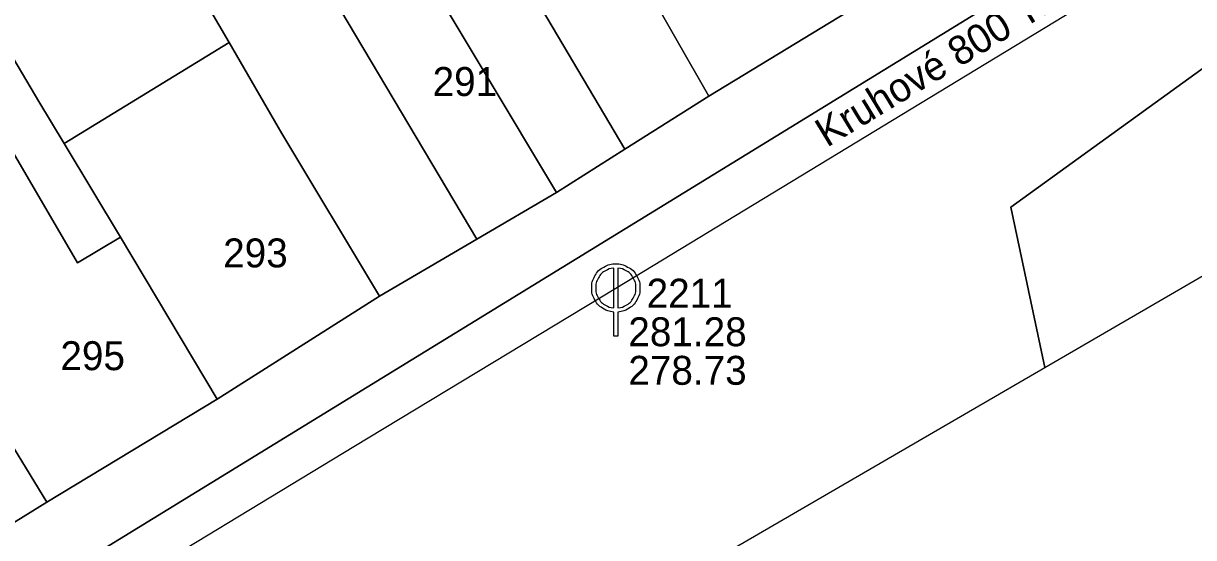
# Model space of a CAD drawing. Extents: x -571312 to -571060, y -1087128 to -1086933.
# Drawn here: x -571153.9 to -571093.3, y -1087060.8 to -1087034.1 of the extents above; entities that cross this region are included whole.
import ezdxf

# ---------------------------------------------------------------- set-up
doc = ezdxf.new("R2010")
doc.units = 0
for name, color, linetype in [('Default', 7, 'Continuous'), ('Kanalizační stoka', 7, 'Continuous'), ('Kanalizační šachta', 7, 'Continuous'), ('Parcela-polygon', 7, 'Continuous'), ('Parcela-text', 7, 'Continuous'), ('Popis kmenové stoky', 7, 'Continuous'), ('Popis šachty', 7, 'Continuous')]:
    doc.layers.add(name, color=color, linetype=linetype)

msp = doc.modelspace()

# ---------------------------------------------------------------- linework, layer by layer
at = {"layer": 'Default'}
for points in [[(-571123.323, -1087049.108), (-571123.581, -1087049.09), (-571123.843, -1087048.944), (-571124.14, -1087048.78), (-571124.305, -1087048.483), (-571124.47, -1087048.185), (-571124.47, -1087047.86), (-571124.47, -1087047.533), (-571124.302, -1087047.233), (-571124.133, -1087046.932), (-571123.835, -1087046.771), (-571123.537, -1087046.61), (-571123.22, -1087046.61), (-571122.905, -1087046.61), (-571122.606, -1087046.771), (-571122.307, -1087046.932), (-571122.138, -1087047.233), (-571121.97, -1087047.533), (-571121.97, -1087047.86), (-571121.97, -1087048.185), (-571122.135, -1087048.483), (-571122.3, -1087048.78), (-571122.597, -1087048.944), (-571122.859, -1087049.09), (-571123.117, -1087049.108)], [(-571123.323, -1087046.822), (-571123.52, -1087046.839), (-571123.735, -1087046.954), (-571123.984, -1087047.089), (-571124.123, -1087047.339), (-571124.262, -1087047.589), (-571124.262, -1087047.86), (-571124.262, -1087048.131), (-571124.126, -1087048.378), (-571123.989, -1087048.624), (-571123.74, -1087048.761), (-571123.528, -1087048.881), (-571123.323, -1087048.895)], [(-571123.117, -1087048.895), (-571122.912, -1087048.881), (-571122.698, -1087048.761), (-571122.451, -1087048.624), (-571122.314, -1087048.378), (-571122.178, -1087048.131), (-571122.178, -1087047.86), (-571122.178, -1087047.589), (-571122.318, -1087047.339), (-571122.458, -1087047.089), (-571122.707, -1087046.954), (-571122.92, -1087046.839), (-571123.117, -1087046.822)]]:
    msp.add_open_spline(points, degree=3, dxfattribs=at)
at = {"layer": 'Kanalizační stoka'}
for points in [[(-571123.22, -1087047.86), (-571104.524, -1087036.501), (-571085.827, -1087025.142)], [(-571150.38, -1087064.31), (-571136.8, -1087056.085), (-571123.22, -1087047.86)]]:
    msp.add_lwpolyline(points, dxfattribs=at)
at = {"layer": 'Kanalizační šachta'}
for points in [[(-571123.323, -1087048.895), (-571123.323, -1087046.822)], [(-571123.117, -1087046.822), (-571123.117, -1087048.895)], [(-571123.117, -1087049.108), (-571123.117, -1087050.36), (-571123.323, -1087050.36), (-571123.323, -1087049.108)]]:
    msp.add_lwpolyline(points, dxfattribs=at)
at = {"layer": 'Parcela-polygon'}
msp.add_line((-571100.979, -1087051.983), (-571073.23, -1087035.86), dxfattribs=at)
for points in [[(-571238.048, -1087115.573), (-571084.13, -1087021.07), (-571088.23, -1087015.62), (-571087.4, -1087014.88), (-571089.5, -1087012.31), (-571106.96, -1086996.89), (-571110.31, -1086993.17), (-571111.37, -1086999.41), (-571102.11, -1087007.86), (-571094.7, -1087015.4), (-571092.99, -1087017.97), (-571091.96, -1087020.97), (-571094.14, -1087023.09), (-571099.22, -1087026.2), (-571108.52, -1087031.9), (-571118.39, -1087037.91), (-571122.75, -1087040.66), (-571126.3, -1087042.9), (-571130.43, -1087045.33), (-571135.47, -1087048.29), (-571143.89, -1087053.63), (-571152.72, -1087058.97), (-571161.7, -1087064.52)], [(-571100.979, -1087051.983), (-571102.73, -1087043.67), (-571081.09, -1087028.01), (-571079.74, -1087027.03), (-571084.13, -1087021.07), (-571238.048, -1087115.573)], [(-571073.23, -1087035.86), (-571079.74, -1087027.03), (-571081.09, -1087028.01), (-571102.73, -1087043.67), (-571100.979, -1087051.983)], [(-571238.048, -1087115.573), (-571230.994, -1087127.523), (-571100.979, -1087051.983)]]:
    msp.add_lwpolyline(points, dxfattribs=at)
for points in [[(-571123.41, -1087006.48), (-571133.26, -1087012.24), (-571128.44, -1087020.34), (-571125.58, -1087018.67), (-571124.4, -1087020.72), (-571123.13, -1087019.98), (-571119.26, -1087026.8), (-571123.4, -1087029.16), (-571118.39, -1087037.91), (-571108.52, -1087031.9), (-571117.3, -1087017.06), (-571117.95, -1087015.94), (-571118.65, -1087014.61)], [(-571133.26, -1087012.24), (-571141.52, -1087017.13), (-571137.45, -1087024.29), (-571126.3, -1087042.9), (-571122.75, -1087040.66), (-571130.01, -1087028.38), (-571131.18, -1087025.46), (-571126.95, -1087022.94), (-571128.44, -1087020.34)], [(-571141.52, -1087017.13), (-571150.57, -1087022.45), (-571146.72, -1087029.14), (-571146.38, -1087029.72), (-571144.87, -1087032.36), (-571143.27, -1087035.13), (-571140.54, -1087039.85), (-571135.47, -1087048.29), (-571130.43, -1087045.33), (-571139.06, -1087030.81), (-571136.82, -1087029.37), (-571138.04, -1087027.46), (-571139.35, -1087025.42), (-571137.45, -1087024.29)], [(-571150.57, -1087022.45), (-571159.39, -1087027.73), (-571155.35, -1087034.47), (-571153.13, -1087038.18), (-571151.82, -1087040.36), (-571143.27, -1087035.13), (-571144.87, -1087032.36), (-571146.38, -1087029.72), (-571146.72, -1087029.14)], [(-571126.95, -1087022.94), (-571131.18, -1087025.46), (-571130.01, -1087028.38), (-571122.75, -1087040.66), (-571118.39, -1087037.91), (-571123.4, -1087029.16)], [(-571137.45, -1087024.29), (-571139.35, -1087025.42), (-571138.04, -1087027.46), (-571136.82, -1087029.37), (-571139.06, -1087030.81), (-571130.43, -1087045.33), (-571126.3, -1087042.9)], [(-571151.82, -1087040.36), (-571153.13, -1087038.18), (-571155.35, -1087034.47), (-571159.39, -1087027.73), (-571168.35, -1087033.04), (-571164.25, -1087040.1), (-571163.6, -1087041.16), (-571162.21, -1087043.44), (-571156.38, -1087040.06), (-571156.31, -1087040.18), (-571155.22, -1087039.59), (-571151.14, -1087046.55), (-571148.91, -1087045.23)], [(-571151.82, -1087040.36), (-571148.91, -1087045.23), (-571143.89, -1087053.63), (-571135.47, -1087048.29), (-571140.54, -1087039.85), (-571143.27, -1087035.13)], [(-571148.91, -1087045.23), (-571151.14, -1087046.55), (-571155.22, -1087039.59), (-571156.31, -1087040.18), (-571156.38, -1087040.06), (-571162.21, -1087043.44), (-571161.09, -1087045.28), (-571152.72, -1087058.97), (-571143.89, -1087053.63)], [(-571161.09, -1087045.28), (-571170.16, -1087050.86), (-571168.8, -1087053.05), (-571161.7, -1087064.52), (-571152.72, -1087058.97)]]:
    msp.add_lwpolyline(points, close=True, dxfattribs=at)

# ---------------------------------------------------------------- texts
at = {"layer": 'Parcela-text'}
for s, p in [('291', (-571132.72, -1087037.9)), ('293', (-571143.58, -1087046.79)), ('295', (-571152.02, -1087052.12))]:
    msp.add_text(s, height=1.5, dxfattribs=at).set_placement(p)
at = {"layer": 'Popis kmenové stoky'}
msp.add_text('Kruhové 800 TZA', height=1.5, rotation=31.28064, dxfattribs=at).set_placement((-571112.274, -1087040.593))
at = {"layer": 'Popis šachty'}
for s, p in [('2211', (-571121.622, -1087048.879)), ('281.28', (-571122.571, -1087050.879)), ('278.73', (-571122.571, -1087052.879))]:
    msp.add_text(s, height=1.5, dxfattribs=at).set_placement(p)

doc.saveas('drawing.dxf')
